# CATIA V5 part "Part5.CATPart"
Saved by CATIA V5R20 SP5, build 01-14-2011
Part number: Part5
Bounding box of the stored display mesh (mm): x -30 to 30, y -30 to 30, z -100 to -80
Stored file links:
  D:\zhonggao\Part5.CATPart
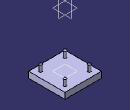
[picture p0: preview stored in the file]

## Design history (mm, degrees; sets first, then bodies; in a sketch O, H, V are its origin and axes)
Body1 (main body)
  Set1
    Plane1: stored without definition
    Sketch1 on Plane1, origin (0, 0, -80), H (1, 0, 0), V (0, 1, 0)
      circle A1 centre (-20, 20) radius 2.5
      circle A2 centre (20, 20) radius 2.5
      circle A3 centre (20, -20) radius 2.5
      circle A4 centre (-20, -20) radius 2.5
      radius A1 = 2.5
      radius A2 = 2.5
      radius A3 = 2.5
      radius A4 = 2.5
  Pad1: profile Sketch1, direction (0, 0, -1), length 10
  Plane2: stored without definition
  Plane3: type Offset, RefPlane Plane2, Offset 10, reversed
  Sketch2 on Plane3, origin (0, 0, -90), H (1, 0, 0), V (0, 1, 0)
    line L1 (30, 30) -> (30, -30)
    line L2 (30, -30) -> (-30, -30)
    line L3 (-30, -30) -> (-30, 30)
    line L4 (-30, 30) -> (30, 30)
    vertical: L1 V, L3 V
    horizontal: L2 H, L4 H
    equidistance: L1 L3 O, L2 L4 O
  Pad2: profile Sketch2, direction (0, 0, -1), length 10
